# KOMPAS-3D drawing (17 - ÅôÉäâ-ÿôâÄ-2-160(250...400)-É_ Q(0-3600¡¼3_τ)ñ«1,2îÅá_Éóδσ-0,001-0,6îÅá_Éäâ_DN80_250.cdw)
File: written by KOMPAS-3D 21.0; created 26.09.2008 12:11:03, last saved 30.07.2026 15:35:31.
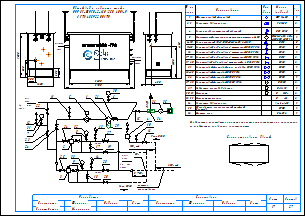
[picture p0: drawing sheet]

Sheets 1-2: A3, landscape

Document properties: Наименование: Макро:21; Автор: RaskoAdmin; Форматы листов документа: 2xA3; Полное имя файла: \\ur38nt01\Departments\КТО\КБ ПУРДГ\Заявки\Прайс-лист на типовые шкафы ГРПШ\ПУРДГ_стандарт_30_04_2026\ПУРДГ с РДГ(Н, В)\ПУРДГ-ШУГО-2-160(250...400)-Р_ Q(0-3600нм3_ч)до1,2МПа_Рвых-0,001-0,6МПа_РДГ_DN80_250.cdw

Title block, sheet 1: Наименование: Пункт учета газа / ПУГ-Ш-400-Р / ЛГТИ.485922.001ТУ; designation: ЛГТИ.03.4411141; sheet number: 1; Количество листов документа: 2; organisation: ООО "ЭЛЬСТЕР Газэлектроника"; Форматы листов документа: A3; stored path: C:\Рабочие документы\Компас\ПУГ\Схема.cdw; Разработал: Устинов; Проверил: Кошкин; Утвердил: Кошкин
Title block, sheet 2: sheet number: 2; stored path: D:\Рабочие документы\Заявки\ПУРДГ\ПУРДГ-ШУЭО-2-100-Р 4411220.cdw; designation, second copy: ЛГТИ.03.4411141-

Views: Вид 1, Вид 2
Referenced files: wcvoit.frw
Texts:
  Normal
  № на
  схеме
  Усл.
  обозн.
  Марка
  (модель)
  Кол.
  Фильтр газовый фланцевый
  ФГ 16-50
  Регулятор давления газа
  РДГ-50
  Клапан предохранительный сбросной
  ПСК DN25
  Измерительный комплекс с ротационным счетчиком Ду50
  СГ-ЭК-Р-(0,2...2,0)-
  Кран кнопочный VE-РАСКО-НЗ-1,6-G1/2-М20
  DN15
  Кран шаровой "под приварку" штуцерный DN20 PN16
  Кран шаровой "под приварку" штуцерный DN25 PN16
  DN20
  DN25
  Кран шаровой "под приварку" штуцерный DN15 PN16
  Кран шаровой "под приварку" штуцерный п/п DN20 PN16
  Кран шаровой фланцевый с мех. приводом DN50 PN16
  Кран шаровой фланцевый DN50 PN16
  Кран шаровой фланцевый DN80 PN16
  Кран шаровой фланцевый DN250 PN16
  DN50
  DN80
  DN250
  Индикатор перепада давления
  Манометр
  Манометр-напоромер
  Обогреватель газогорелочный шкафной
  (Эльтон")
  Счетчик газа
  Delta 15
  0...     МПа
  0...     кПа
  Venio-A-15
  ОГШН
  BK-G1,6
  Выход газа
  Вход газа
  logo-rasko-ge.png
  DN 1
  местное
  сопротивление
  Римп DN20
  Выход
  газа
  Р=     кПа
  Вход
  Р=       МПа
  PDI
  Схема открывания дверей
  Предприятие изготовитель может заменять комплектующие на аналогичные,
  не ухудшающие заявленных характеристик.
  Общий вид и габариты шкафа
  ПУРДГ-ШУГО-2-160(250...400)-Р
  Должность
  Конструктор
  Фамилия
  Подпись
  Дата
  Согласовано
  Максимкин
  Лист
  Листов
  POLYLINE_STYLE_0.18_RGB_0_0_0
  POLYLINE_STYLE_0.50_RGB_0_0_0
  POLYLINE_STYLE_0.34_RGB_0_0_0
  PHANTOM_RGB_0_0_0_SC_1_THICK_0.18
  K5LT_THIN_RGB_0_0_0_THICK_0.18
  K5LT32769_RGB_0_0_0_THICK_0.18
  K5LT12_RGB_0_0_0_SC_1_THICK_0.18
  K5LT_DASHED_RGB_0_0_0_SC_1_THICK_0.18
  ACISOTGL_RGB_0_0_0_SC_0.8_THICK_0.25
  CONTINUOUS_RGB_0_127_31_THICK_0.3
  CONTINUOUS_RGB_0_0_255_THICK_0.35
  CONTINUOUS_RGB_255_0_0_THICK_0.35
  POLYLINE_STYLE_0.25_RGB_0_0_0
  CONTINUOUS_RGB_0_0_0_THICK_0.5
  POLYLINE_STYLE_0.35_RGB_0_0_255
  CONTINUOUS_RGB_0_0_0_THICK_0.4
  CONTINUOUS_RGB_0_0_0_THICK_0.35
  НЕВИДИМАЯ_RGB_0_0_0_SC_0.3_THICK_0.25
  СONTINUOUS_RGB_0_0_0_THICK_0.25
  ОСЕВАЯ2_RGB_248_153_30_SC_0.3_THICK_0.25
  Без оформления
Dimensions and other numbers on the sheet: 1; 2, 3; 2; 4; 5; -160(250; 400)/1,6; 6-10; 11-15; 16; 17, 18; 19, 20; 21; 22-25; 26; 27, 28; 29; 30, 31; 32, 33; 34; 35; 36; 1500; 450; 500; 1200; 550; 305; 3600; 4130; 2000; 3900; 5,,,7DN 1; 7; 31; 12; 22; 23; 24; 11; 6; 30; 32; 8; 13; 27; 19; 10; 25; 33; 9; 3; 14; 28; 20; 17; 18; 15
